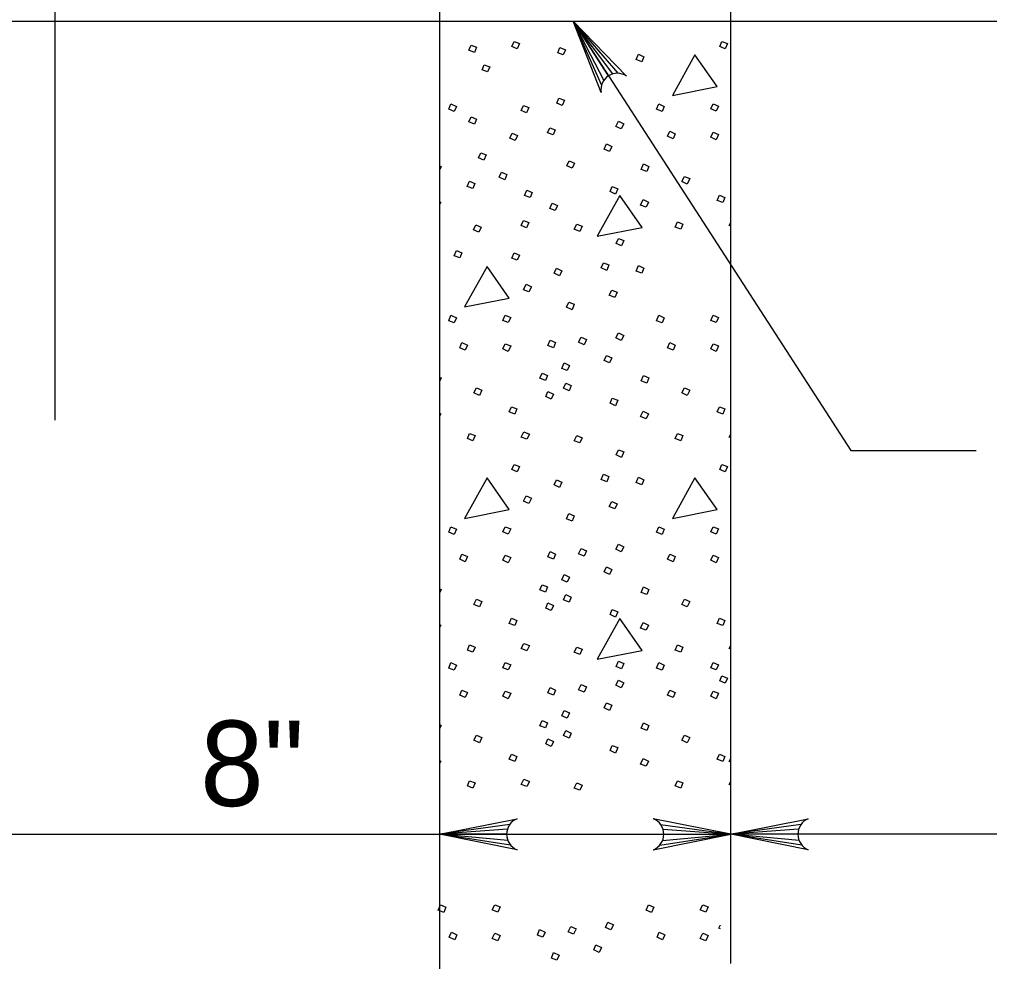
# Model space of a CAD drawing. Extents: x 0 to 34, y 0 to 22.
# Drawn here: x 8.046 to 9.818, y 3.328 to 5.05 of the extents above; entities that cross this region are included whole.
import ezdxf

# ---------------------------------------------------------------- set-up
doc = ezdxf.new("R2010")
doc.units = 0
doc.layers.add('Default', color=7, linetype='Continuous')

msp = doc.modelspace()

# ---------------------------------------------------------------- linework, layer by layer
at = {"layer": 'Default'}
for p, q in [((8.1105, 6.2114), (8.1105, 4.3177)), ((8.8136, 5.8753), (8.8136, 2.1752)), ((9.3457, 3.325), (9.3457, 5.3462)), ((6.0455, 5.0471), (8.8136, 5.0471)), ((8.8136, 5.0471), (9.3457, 5.0471)), ((9.122, 4.947), (9.058, 5.0471)), ((9.1138, 4.9391), (9.058, 5.0471)), ((9.1096, 4.9307), (9.058, 5.0471)), ((9.1302, 4.9507), (9.058, 5.0471)), ((9.1397, 4.9517), (9.058, 5.0471)), ((9.058, 5.0471), (9.5652, 4.2626)), ((9.3457, 5.0471), (11.7202, 5.0471)), ((9.5652, 4.2626), (9.794, 4.2626)), ((8.9418, 3.579), (8.8136, 3.561)), ((8.9375, 3.5701), (8.8136, 3.561)), ((9.2175, 3.579), (9.3457, 3.561)), ((9.2219, 3.5701), (9.3457, 3.561)), ((9.4739, 3.579), (9.3457, 3.561)), ((9.4695, 3.5701), (9.3457, 3.561)), ((7.9553, 3.561), (9.3457, 3.561)), ((8.9361, 3.561), (8.8136, 3.561)), ((8.9384, 3.5495), (8.8136, 3.561)), ((8.9433, 3.5412), (8.8136, 3.561)), ((9.216, 3.5412), (9.3457, 3.561)), ((9.2209, 3.5495), (9.3457, 3.561)), ((9.2232, 3.561), (9.3457, 3.561)), ((11.7202, 3.561), (9.3457, 3.561)), ((9.4682, 3.561), (9.3457, 3.561)), ((9.4705, 3.5495), (9.3457, 3.561)), ((9.4754, 3.5412), (9.3457, 3.561))]:
    msp.add_line(p, q, dxfattribs=at)
for points in [[(9.1089, 4.9166), (9.058, 5.0471), (9.1552, 4.9462)], [(8.8714, 5.0031), (8.8814, 4.9991), (8.8774, 4.9897), (8.8674, 4.9937), (8.8714, 5.0031)], [(8.9497, 5.0098), (8.9597, 5.0058), (8.9557, 4.9965), (8.9457, 5.0005), (8.9497, 5.0098)], [(9.0334, 4.9986), (9.0434, 4.9946), (9.0394, 4.9852), (9.0294, 4.9892), (9.0334, 4.9986)], [(9.3295, 5.0098), (9.3395, 5.0058), (9.3355, 4.9965), (9.3255, 5.0005), (9.3295, 5.0098)], [(9.1769, 4.9865), (9.1869, 4.9818), (9.1829, 4.9725), (9.1729, 4.9765), (9.1769, 4.9865)], [(9.2802, 4.9852), (9.2389, 4.9112), (9.3209, 4.9272), (9.2802, 4.9852)], [(8.8952, 4.9673), (8.9052, 4.9633), (8.9012, 4.954), (8.8912, 4.958), (8.8952, 4.9673)], [(8.8344, 4.8958), (8.8444, 4.8912), (8.8404, 4.8819), (8.8304, 4.8859), (8.8344, 4.8958)], [(8.9667, 4.8928), (8.9767, 4.8888), (8.9727, 4.8795), (8.9627, 4.8835), (8.9667, 4.8928)], [(9.0318, 4.9062), (9.0418, 4.9022), (9.0378, 4.8929), (9.0278, 4.8969), (9.0318, 4.9062)], [(9.2142, 4.8958), (9.2242, 4.8912), (9.2202, 4.8819), (9.2102, 4.8859), (9.2142, 4.8958)], [(9.3135, 4.8958), (9.3235, 4.8918), (9.3189, 4.8826), (9.3089, 4.8865), (9.3135, 4.8958)], [(8.8714, 4.8719), (8.8814, 4.8679), (8.8774, 4.8586), (8.8674, 4.8626), (8.8714, 4.8719)], [(9.1403, 4.8639), (9.1503, 4.8592), (9.1456, 4.8499), (9.1356, 4.8546), (9.1403, 4.8639)], [(8.946, 4.8422), (8.956, 4.8382), (8.952, 4.8288), (8.942, 4.8328), (8.946, 4.8422)], [(9.015, 4.8522), (9.025, 4.8482), (9.021, 4.8389), (9.011, 4.8429), (9.015, 4.8522)], [(9.2342, 4.8459), (9.2442, 4.8412), (9.2402, 4.8319), (9.2302, 4.8366), (9.2342, 4.8459)], [(9.3135, 4.8439), (9.3235, 4.8399), (9.3189, 4.8299), (9.3089, 4.8346), (9.3135, 4.8439)], [(9.1183, 4.8226), (9.1283, 4.8179), (9.1243, 4.8086), (9.1143, 4.8132), (9.1183, 4.8226)], [(8.8888, 4.8063), (8.8988, 4.8023), (8.8948, 4.7931), (8.8849, 4.7971), (8.8888, 4.8063)], [(9.0501, 4.7916), (9.0601, 4.7876), (9.0561, 4.7782), (9.0461, 4.7822), (9.0501, 4.7916)], [(9.1862, 4.7859), (9.1962, 4.7812), (9.1922, 4.7719), (9.1822, 4.7759), (9.1862, 4.7859)], [(8.8136, 4.7826), (8.8164, 4.7812), (8.8136, 4.7747)], [(8.9268, 4.7712), (8.9368, 4.7665), (8.9328, 4.7572), (8.9228, 4.7618), (8.9268, 4.7712)], [(8.8682, 4.7542), (8.8782, 4.7502), (8.8742, 4.7409), (8.8642, 4.7449), (8.8682, 4.7542)], [(9.2609, 4.7632), (9.2709, 4.7592), (9.2662, 4.7492), (9.2562, 4.7539), (9.2609, 4.7632)], [(8.973, 4.7378), (8.983, 4.7338), (8.979, 4.7245), (8.969, 4.7285), (8.973, 4.7378)], [(9.129, 4.7447), (9.139, 4.7407), (9.135, 4.7307), (9.125, 4.7353), (9.129, 4.7447)], [(8.8136, 4.717), (8.8157, 4.716), (8.8136, 4.7117)], [(9.143, 4.728), (9.1016, 4.654), (9.1835, 4.67), (9.143, 4.728)], [(9.1855, 4.7207), (9.1955, 4.716), (9.1909, 4.7067), (9.1809, 4.7107), (9.1855, 4.7207)], [(9.3249, 4.7287), (9.3349, 4.7247), (9.3309, 4.7153), (9.3209, 4.7193), (9.3249, 4.7287)], [(9.0191, 4.714), (9.0291, 4.71), (9.0251, 4.7007), (9.0151, 4.7047), (9.0191, 4.714)], [(8.9667, 4.6827), (8.9767, 4.6787), (8.9727, 4.6693), (8.9627, 4.6733), (8.9667, 4.6827)], [(9.2482, 4.68), (9.2582, 4.676), (9.2542, 4.6667), (9.2442, 4.6707), (9.2482, 4.68)], [(9.3457, 4.6722), (9.3428, 4.6733), (9.3457, 4.6791)], [(8.8796, 4.6747), (8.8896, 4.6707), (8.8856, 4.6614), (8.8756, 4.6654), (8.8796, 4.6747)], [(9.0643, 4.676), (9.0743, 4.672), (9.0696, 4.6627), (9.0596, 4.6667), (9.0643, 4.676)], [(9.1403, 4.65), (9.1503, 4.646), (9.1463, 4.636), (9.1363, 4.6407), (9.1403, 4.65)], [(8.8444, 4.6276), (8.8544, 4.6236), (8.8504, 4.6142), (8.8404, 4.6182), (8.8444, 4.6276)], [(8.9497, 4.6233), (8.9597, 4.6193), (8.9557, 4.61), (8.9457, 4.614), (8.9497, 4.6233)], [(8.9004, 4.5987), (8.859, 4.5247), (8.941, 4.5407), (8.9004, 4.5987)], [(9.027, 4.5954), (9.037, 4.5907), (9.033, 4.5814), (9.023, 4.5861), (9.027, 4.5954)], [(9.113, 4.6053), (9.123, 4.6013), (9.119, 4.5914), (9.109, 4.5961), (9.113, 4.6053)], [(9.1769, 4.6001), (9.1869, 4.5954), (9.1829, 4.5861), (9.1729, 4.5901), (9.1769, 4.6001)], [(8.9717, 4.5661), (8.9817, 4.5614), (8.977, 4.5521), (8.967, 4.5561), (8.9717, 4.5661)], [(9.1283, 4.5554), (9.1383, 4.5514), (9.1336, 4.5421), (9.1236, 4.5461), (9.1283, 4.5554)], [(9.0496, 4.5334), (9.0596, 4.5294), (9.0556, 4.5194), (9.0456, 4.5241), (9.0496, 4.5334)], [(8.8344, 4.5094), (8.8444, 4.5047), (8.8404, 4.4954), (8.8304, 4.4994), (8.8344, 4.5094)], [(8.9337, 4.5094), (8.9437, 4.5054), (8.939, 4.4961), (8.929, 4.5001), (8.9337, 4.5094)], [(9.2142, 4.5094), (9.2242, 4.5047), (9.2202, 4.4954), (9.2102, 4.4994), (9.2142, 4.5094)], [(9.3135, 4.5094), (9.3235, 4.5054), (9.3189, 4.4961), (9.3089, 4.5001), (9.3135, 4.5094)], [(9.0723, 4.4694), (9.0823, 4.4654), (9.0776, 4.4555), (9.0676, 4.4601), (9.0723, 4.4694)], [(9.1403, 4.4774), (9.1503, 4.4727), (9.1456, 4.4634), (9.1356, 4.4681), (9.1403, 4.4774)], [(8.8544, 4.4595), (8.8644, 4.4548), (8.8604, 4.4455), (8.8504, 4.4502), (8.8544, 4.4595)], [(8.9337, 4.4575), (8.9437, 4.4535), (8.939, 4.4435), (8.929, 4.4482), (8.9337, 4.4575)], [(9.0156, 4.4641), (9.0256, 4.4595), (9.0216, 4.4502), (9.0116, 4.4542), (9.0156, 4.4641)], [(9.2342, 4.4595), (9.2442, 4.4548), (9.2402, 4.4455), (9.2302, 4.4502), (9.2342, 4.4595)], [(9.3135, 4.4575), (9.3235, 4.4535), (9.3189, 4.4435), (9.3089, 4.4482), (9.3135, 4.4575)], [(9.1183, 4.4362), (9.1283, 4.4315), (9.1243, 4.4222), (9.1143, 4.4268), (9.1183, 4.4362)], [(9.041, 4.4222), (9.051, 4.4175), (9.047, 4.4082), (9.037, 4.4122), (9.041, 4.4222)], [(8.8136, 4.3962), (8.8164, 4.3948), (8.8136, 4.3883)], [(9.001, 4.4035), (9.011, 4.3995), (9.007, 4.3902), (8.997, 4.3942), (9.001, 4.4035)], [(9.1862, 4.3995), (9.1962, 4.3948), (9.1922, 4.3855), (9.1822, 4.3895), (9.1862, 4.3995)], [(9.0443, 4.3855), (9.0543, 4.3808), (9.0503, 4.3715), (9.0403, 4.3762), (9.0443, 4.3855)], [(8.881, 4.3768), (8.891, 4.3728), (8.8864, 4.3628), (8.8764, 4.3675), (8.881, 4.3768)], [(9.0116, 4.3702), (9.0216, 4.3655), (9.0176, 4.3562), (9.0076, 4.3608), (9.0116, 4.3702)], [(9.2609, 4.3768), (9.2709, 4.3728), (9.2662, 4.3628), (9.2562, 4.3675), (9.2609, 4.3768)], [(9.129, 4.3582), (9.139, 4.3542), (9.135, 4.3442), (9.125, 4.3488), (9.129, 4.3582)], [(8.8136, 4.3305), (8.8157, 4.3295), (8.8136, 4.3252)], [(8.945, 4.3422), (8.955, 4.3382), (8.951, 4.3288), (8.941, 4.3328), (8.945, 4.3422)], [(9.1855, 4.3342), (9.1955, 4.3295), (9.1909, 4.3202), (9.1809, 4.3242), (9.1855, 4.3342)], [(9.3249, 4.3422), (9.3349, 4.3382), (9.3309, 4.3288), (9.3209, 4.3328), (9.3249, 4.3422)], [(8.8684, 4.2936), (8.8784, 4.2896), (8.8744, 4.2802), (8.8644, 4.2842), (8.8684, 4.2936)], [(8.9677, 4.2962), (8.9777, 4.2922), (8.973, 4.2829), (8.963, 4.2869), (8.9677, 4.2962)], [(9.0643, 4.2896), (9.0743, 4.2856), (9.0696, 4.2762), (9.0596, 4.2802), (9.0643, 4.2896)], [(9.2482, 4.2936), (9.2582, 4.2896), (9.2542, 4.2802), (9.2442, 4.2842), (9.2482, 4.2936)], [(9.3457, 4.2857), (9.3428, 4.2869), (9.3457, 4.2926)], [(9.1403, 4.2636), (9.1503, 4.2596), (9.1463, 4.2496), (9.1363, 4.2542), (9.1403, 4.2636)], [(8.9497, 4.2369), (8.9597, 4.2329), (8.9557, 4.2236), (8.9457, 4.2276), (8.9497, 4.2369)], [(9.3295, 4.2369), (9.3395, 4.2329), (9.3355, 4.2236), (9.3255, 4.2276), (9.3295, 4.2369)], [(9.113, 4.2189), (9.123, 4.2149), (9.119, 4.2049), (9.109, 4.2096), (9.113, 4.2189)], [(8.9004, 4.2122), (8.859, 4.1383), (8.941, 4.1543), (8.9004, 4.2122)], [(9.027, 4.2089), (9.037, 4.2042), (9.033, 4.1949), (9.023, 4.1996), (9.027, 4.2089)], [(9.1769, 4.2136), (9.1869, 4.2089), (9.1829, 4.1996), (9.1729, 4.2036), (9.1769, 4.2136)], [(9.2802, 4.2122), (9.2389, 4.1383), (9.3209, 4.1543), (9.2802, 4.2122)], [(8.9717, 4.1796), (8.9817, 4.1749), (8.977, 4.1656), (8.967, 4.1697), (8.9717, 4.1796)], [(9.1283, 4.169), (9.1383, 4.165), (9.1336, 4.1557), (9.1236, 4.1597), (9.1283, 4.169)], [(9.0496, 4.147), (9.0596, 4.143), (9.0556, 4.133), (9.0456, 4.1377), (9.0496, 4.147)], [(8.8344, 4.123), (8.8444, 4.1183), (8.8404, 4.109), (8.8304, 4.113), (8.8344, 4.123)], [(8.9337, 4.123), (8.9437, 4.119), (8.939, 4.1097), (8.929, 4.1137), (8.9337, 4.123)], [(9.2142, 4.123), (9.2242, 4.1183), (9.2202, 4.109), (9.2102, 4.113), (9.2142, 4.123)], [(9.3135, 4.123), (9.3235, 4.119), (9.3189, 4.1097), (9.3089, 4.1137), (9.3135, 4.123)], [(9.0156, 4.0777), (9.0256, 4.073), (9.0216, 4.0637), (9.0116, 4.0677), (9.0156, 4.0777)], [(9.0723, 4.083), (9.0823, 4.079), (9.0776, 4.069), (9.0676, 4.0737), (9.0723, 4.083)], [(9.1403, 4.091), (9.1503, 4.0863), (9.1456, 4.077), (9.1356, 4.0817), (9.1403, 4.091)], [(8.8544, 4.073), (8.8644, 4.0683), (8.8604, 4.059), (8.8504, 4.0637), (8.8544, 4.073)], [(8.9337, 4.071), (8.9437, 4.067), (8.939, 4.057), (8.929, 4.0617), (8.9337, 4.071)], [(9.2342, 4.073), (9.2442, 4.0683), (9.2402, 4.059), (9.2302, 4.0637), (9.2342, 4.073)], [(9.3135, 4.071), (9.3235, 4.067), (9.3189, 4.057), (9.3089, 4.0617), (9.3135, 4.071)], [(9.1183, 4.0497), (9.1283, 4.045), (9.1243, 4.0357), (9.1143, 4.0403), (9.1183, 4.0497)], [(9.041, 4.0357), (9.051, 4.031), (9.047, 4.0217), (9.037, 4.0257), (9.041, 4.0357)], [(8.8136, 4.0097), (8.8164, 4.0084), (8.8136, 4.0018)], [(9.001, 4.0171), (9.011, 4.0131), (9.007, 4.0037), (8.997, 4.0077), (9.001, 4.0171)], [(9.1862, 4.0131), (9.1962, 4.0084), (9.1922, 3.9991), (9.1822, 4.0031), (9.1862, 4.0131)], [(8.881, 3.9904), (8.891, 3.9864), (8.8864, 3.9764), (8.8764, 3.9811), (8.881, 3.9904)], [(9.0443, 3.9991), (9.0543, 3.9944), (9.0503, 3.9851), (9.0403, 3.9897), (9.0443, 3.9991)], [(9.2609, 3.9904), (9.2709, 3.9864), (9.2662, 3.9764), (9.2562, 3.9811), (9.2609, 3.9904)], [(9.0116, 3.9837), (9.0216, 3.9791), (9.0176, 3.9697), (9.0076, 3.9744), (9.0116, 3.9837)], [(9.129, 3.9717), (9.139, 3.9677), (9.135, 3.9577), (9.125, 3.9624), (9.129, 3.9717)], [(8.945, 3.9557), (8.955, 3.9517), (8.951, 3.9424), (8.941, 3.9464), (8.945, 3.9557)], [(9.143, 3.9551), (9.1016, 3.8812), (9.1835, 3.8971), (9.143, 3.9551)], [(9.3249, 3.9557), (9.3349, 3.9517), (9.3309, 3.9424), (9.3209, 3.9464), (9.3249, 3.9557)], [(8.8136, 3.9441), (8.8157, 3.9431), (8.8136, 3.9388)], [(9.1855, 3.9477), (9.1955, 3.9431), (9.1909, 3.9337), (9.1809, 3.9377), (9.1855, 3.9477)], [(8.8684, 3.9071), (8.8784, 3.9031), (8.8744, 3.8937), (8.8644, 3.8977), (8.8684, 3.9071)], [(8.9677, 3.9097), (8.9777, 3.9057), (8.973, 3.8964), (8.963, 3.9004), (8.9677, 3.9097)], [(9.0643, 3.9031), (9.0743, 3.8991), (9.0696, 3.8897), (9.0596, 3.8937), (9.0643, 3.9031)], [(9.2482, 3.9071), (9.2582, 3.9031), (9.2542, 3.8937), (9.2442, 3.8977), (9.2482, 3.9071)], [(9.3457, 3.8993), (9.3428, 3.9004), (9.3457, 3.9062)], [(8.8344, 3.8746), (8.8444, 3.8699), (8.8404, 3.8606), (8.8304, 3.8646), (8.8344, 3.8746)], [(8.9337, 3.8746), (8.9437, 3.8706), (8.939, 3.8612), (8.929, 3.8652), (8.9337, 3.8746)], [(9.1403, 3.8772), (9.1503, 3.8731), (9.1463, 3.8632), (9.1363, 3.8678), (9.1403, 3.8772)], [(9.2142, 3.8746), (9.2242, 3.8699), (9.2202, 3.8606), (9.2102, 3.8646), (9.2142, 3.8746)], [(9.3135, 3.8746), (9.3235, 3.8706), (9.3189, 3.8612), (9.3089, 3.8652), (9.3135, 3.8746)], [(9.3295, 3.8505), (9.3395, 3.8465), (9.3355, 3.8372), (9.3255, 3.8412), (9.3295, 3.8505)], [(9.0156, 3.8292), (9.0256, 3.8246), (9.0216, 3.8152), (9.0116, 3.8193), (9.0156, 3.8292)], [(9.0723, 3.8346), (9.0823, 3.8306), (9.0776, 3.8206), (9.0676, 3.8252), (9.0723, 3.8346)], [(9.1403, 3.8426), (9.1503, 3.8379), (9.1456, 3.8286), (9.1356, 3.8332), (9.1403, 3.8426)], [(8.8544, 3.8246), (8.8644, 3.8199), (8.8604, 3.8107), (8.8504, 3.8152), (8.8544, 3.8246)], [(8.9337, 3.8226), (8.9437, 3.8186), (8.939, 3.8087), (8.929, 3.8132), (8.9337, 3.8226)], [(9.2342, 3.8246), (9.2442, 3.8199), (9.2402, 3.8107), (9.2302, 3.8152), (9.2342, 3.8246)], [(9.3135, 3.8226), (9.3235, 3.8186), (9.3189, 3.8087), (9.3089, 3.8132), (9.3135, 3.8226)], [(9.1183, 3.8013), (9.1283, 3.7967), (9.1243, 3.7873), (9.1143, 3.792), (9.1183, 3.8013)], [(9.041, 3.7873), (9.051, 3.7827), (9.047, 3.7733), (9.037, 3.7773), (9.041, 3.7873)], [(8.8136, 3.7613), (8.8164, 3.76), (8.8136, 3.7534)], [(9.001, 3.7687), (9.011, 3.7647), (9.007, 3.7553), (8.997, 3.7593), (9.001, 3.7687)], [(9.1862, 3.7647), (9.1962, 3.76), (9.1922, 3.7507), (9.1822, 3.7547), (9.1862, 3.7647)], [(8.881, 3.742), (8.891, 3.738), (8.8864, 3.728), (8.8764, 3.7327), (8.881, 3.742)], [(9.0443, 3.7507), (9.0543, 3.746), (9.0503, 3.7367), (9.0403, 3.7413), (9.0443, 3.7507)], [(9.2609, 3.742), (9.2709, 3.738), (9.2662, 3.728), (9.2562, 3.7327), (9.2609, 3.742)], [(9.0116, 3.7353), (9.0216, 3.7307), (9.0176, 3.7213), (9.0076, 3.726), (9.0116, 3.7353)], [(9.129, 3.7233), (9.139, 3.7193), (9.135, 3.7093), (9.125, 3.714), (9.129, 3.7233)], [(8.945, 3.7073), (8.955, 3.7033), (8.951, 3.694), (8.941, 3.698), (8.945, 3.7073)], [(9.3249, 3.7073), (9.3349, 3.7033), (9.3309, 3.694), (9.3209, 3.698), (9.3249, 3.7073)], [(8.8136, 3.6957), (8.8157, 3.6947), (8.8136, 3.6904)], [(9.1855, 3.6993), (9.1955, 3.6947), (9.1909, 3.6853), (9.1809, 3.6893), (9.1855, 3.6993)], [(9.3457, 3.6928), (9.3428, 3.694), (9.3457, 3.6997)], [(8.8684, 3.6587), (8.8784, 3.6547), (8.8744, 3.6454), (8.8644, 3.6494), (8.8684, 3.6587)], [(8.9677, 3.6614), (8.9777, 3.6574), (8.973, 3.6481), (8.963, 3.6521), (8.9677, 3.6614)], [(9.0643, 3.6547), (9.0743, 3.6507), (9.0696, 3.6414), (9.0596, 3.6454), (9.0643, 3.6547)], [(9.2482, 3.6587), (9.2582, 3.6547), (9.2542, 3.6454), (9.2442, 3.6494), (9.2482, 3.6587)], [(9.3457, 3.6509), (9.3428, 3.6521), (9.3457, 3.6577)], [(8.9552, 3.5327), (8.8136, 3.561), (8.9552, 3.5893)], [(9.2041, 3.5327), (9.3457, 3.561), (9.2041, 3.5893)], [(9.4873, 3.5327), (9.3457, 3.561), (9.4873, 3.5893)], [(8.8153, 3.4322), (8.8253, 3.4275), (8.8213, 3.4182), (8.8113, 3.4222), (8.8153, 3.4322)], [(8.9146, 3.4322), (8.9246, 3.4282), (8.92, 3.4188), (8.91, 3.4228), (8.9146, 3.4322)], [(9.1951, 3.4322), (9.2051, 3.4275), (9.2011, 3.4182), (9.1911, 3.4222), (9.1951, 3.4322)], [(9.2945, 3.4322), (9.3044, 3.4282), (9.2998, 3.4188), (9.2898, 3.4228), (9.2945, 3.4322)], [(8.9965, 3.3868), (9.0065, 3.3822), (9.0025, 3.3728), (8.9925, 3.3768), (8.9965, 3.3868)], [(9.0532, 3.3922), (9.0632, 3.3882), (9.0585, 3.3782), (9.0485, 3.3828), (9.0532, 3.3922)], [(9.1212, 3.4002), (9.1311, 3.3955), (9.1265, 3.3862), (9.1165, 3.3908), (9.1212, 3.4002)], [(9.3266, 3.3885), (9.3237, 3.3896), (9.3266, 3.3953)], [(8.8353, 3.3822), (8.8453, 3.3775), (8.8413, 3.3682), (8.8313, 3.3728), (8.8353, 3.3822)], [(8.9146, 3.3802), (8.9246, 3.3762), (8.92, 3.3662), (8.91, 3.3708), (8.9146, 3.3802)], [(9.2151, 3.3822), (9.2251, 3.3775), (9.2211, 3.3682), (9.2111, 3.3728), (9.2151, 3.3822)], [(9.2945, 3.3802), (9.3044, 3.3762), (9.2998, 3.3662), (9.2898, 3.3708), (9.2945, 3.3802)], [(9.0992, 3.3588), (9.1092, 3.3542), (9.1052, 3.3449), (9.0952, 3.3496), (9.0992, 3.3588)], [(9.0219, 3.3449), (9.0319, 3.3402), (9.0279, 3.3309), (9.0179, 3.3349), (9.0219, 3.3449)]]:
    msp.add_lwpolyline(points, dxfattribs=at)
for centre, start, end in [((8.9667, 3.561), 112.0878, 247.9139), ((9.1927, 3.561), 292.0861, 67.9122), ((9.4987, 3.561), 112.0878, 247.9139)]:
    msp.add_arc(centre, 0.0306, start, end, dxfattribs=at)
msp.add_ellipse((9.1381, 4.922), major_axis=(0.0178, 0.0237), ratio=0.999895, start_param=0.02948, end_param=2.400093, dxfattribs=at)

# ---------------------------------------------------------------- texts
msp.add_text('8"', height=0.156, dxfattribs=at).set_placement((8.3763, 3.6126))

doc.saveas('drawing.dxf')
